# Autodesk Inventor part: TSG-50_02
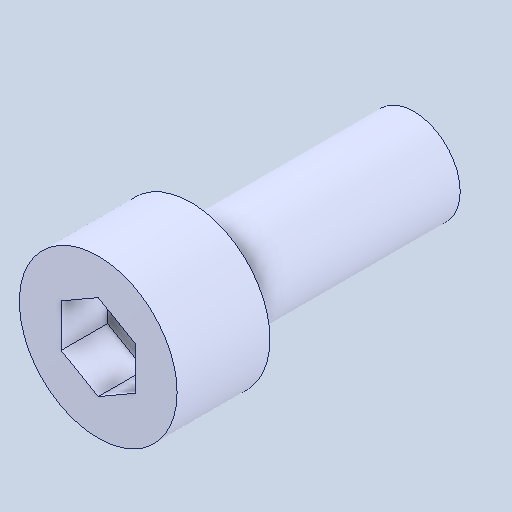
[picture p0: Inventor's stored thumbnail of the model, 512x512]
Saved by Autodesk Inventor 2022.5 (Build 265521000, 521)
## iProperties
Created: 2024-05
Part Number: TSG-50_02
Material: 一般
Document SubType Name: Modeling
Designer: ImaoCorp
Density: 1 g/cm^3
Appearance: 既定
Author: ImaoCorp
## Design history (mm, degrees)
feature "TSG-50_02"
node "ソリッド1"
